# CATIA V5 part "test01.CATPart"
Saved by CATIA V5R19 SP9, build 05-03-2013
Part number: test01
Bounding box of the stored display mesh (mm): x 0 to 100, y 0 to 50, z 0 to 20
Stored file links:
  P:\_sw\STEP\test01.CATPart
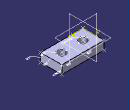
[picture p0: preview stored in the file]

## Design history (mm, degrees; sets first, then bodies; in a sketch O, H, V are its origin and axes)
TTRSSet1
f4a2d38f3ddc11d3a929006094b99c4b_11 "CATTPSSet"
Set1 "GS1"
  Point1 to Point10: stored without definition
Body1 (main body)
  Sketch1 on xy-plane, origin (0, 0, 0), H (1, 0, 0), V (0, 1, 0)
    line L1 (0, 0) -> (100, 0)
    line L2 (100, 0) -> (100, 50)
    line L3 (100, 50) -> (0, 50)
    line L4 (0, 50) -> (0, 0)
    length L1 = 100
    length L2 = 50
    horizontal: L1 H, L3 H
    vertical: L2 V, L4 V
  Pad1: profile Sketch1, direction (0, 0, 1), length 20
  Sketch2 on end face of Pad1, origin (0, 0, 20), H (1, 0, 0), V (0, 1, 0)
    circle A1 centre (25, 25) radius 10
    point P1 (25, 25)
    circle A2 centre (75, 25) radius 10
    point P2 (75, 25)
    reference projected line E1 (0, 50) -> (0, 0) from edge [face of Pad1 from Sketch1.L4 | end face of Pad1]
    reference projected line E2 (0, 0) -> (100, 0) from edge [face of Pad1 from Sketch1.L1 | end face of Pad1]
    reference projected line E3 (0, 0) -> (100, 0) from edge [face of Pad1 from Sketch1.L1 | end face of Pad1]
    distance P1 E1 = 25
    distance P1 P2 = 50
    distance P1 E2 = 25
    distance P2 E3 = 25
    radius A1 = 10
    radius A2 = 10
  Pocket1: profile Sketch2, direction (0, 0, -1), through (limit type 6)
